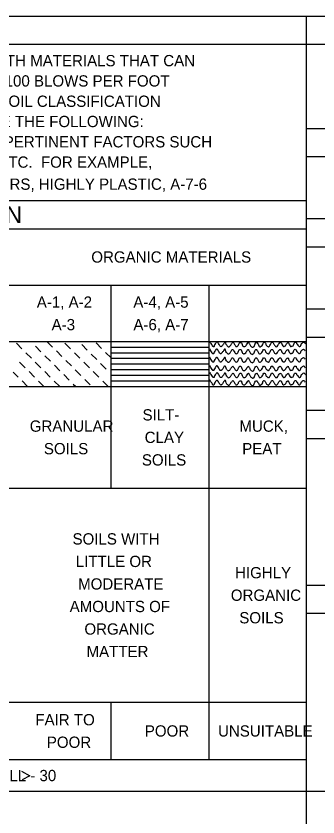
# Model space of a CAD drawing. Extents: x 265553 to 275568, y 168312 to 173522.
# Drawn here: x 267186.1 to 267302.4, y 170743.9 to 171052.1 of the extents above; entities that cross this region are included whole.
import ezdxf

# ---------------------------------------------------------------- set-up
doc = ezdxf.new("R2010")
doc.units = 0
doc.layers.add('Geotech Sheets and Borders Cell', color=7, linetype='Continuous')

msp = doc.modelspace()

# ---------------------------------------------------------------- linework, layer by layer
at = {"layer": 'Geotech Sheets and Borders Cell'}
for p, q in [((266920.42, 171052.08), (268420.42, 171052.08)), ((267297.82, 171052.08), (267297.82, 170249.94)), ((266920.42, 171041.24), (268420.42, 171041.24)), ((267670.42, 171008.7), (267297.82, 171008.7)), ((267670.42, 170997.86), (267297.82, 170997.86)), ((266920.42, 170981.07), (267297.82, 170981.07)), ((267670.42, 170974), (267297.82, 170974)), ((266920.42, 170970.22), (267297.82, 170970.22)), ((267670.42, 170963.15), (267297.82, 170963.15)), ((266920.42, 170948.53), (267297.82, 170948.53)), ((267222.78, 170870.45), (267222.78, 170948.53)), ((267260.52, 170765.99), (267260.52, 170948.53)), ((267670.42, 170939.29), (267297.82, 170939.29)), ((266920.42, 170926.84), (267297.82, 170926.84)), ((267188.37, 170924.06), (267186.25, 170926.19)), ((267198.01, 170926.84), (267200.13, 170924.72)), ((267207.07, 170924.06), (267204.95, 170926.19)), ((267211.41, 170925.67), (267213.54, 170923.54)), ((267219.09, 170924.19), (267216.96, 170926.32)), ((267670.42, 170928.45), (267297.82, 170928.45)), ((267192.02, 170920.42), (267189.89, 170922.55)), ((267195.71, 170922.89), (267193.58, 170925.02)), ((267201.65, 170923.2), (267203.77, 170921.07)), ((267210.72, 170920.42), (267208.59, 170922.55)), ((267222.73, 170920.55), (267220.61, 170922.68)), ((267222.78, 170924.72), (267260.52, 170924.72)), ((267222.78, 170922.55), (267260.52, 170922.55)), ((267260.78, 170924.02), (267260.73, 170923.98)), ((267199.35, 170919.25), (267197.22, 170921.38)), ((267205.29, 170919.55), (267207.42, 170917.43)), ((267215.05, 170922.03), (267217.18, 170919.9)), ((267222.78, 170920.38), (267260.52, 170920.38)), ((267260.78, 170920.81), (267260.73, 170920.77)), ((267189.59, 170916.78), (267187.46, 170918.9)), ((267195.66, 170916.78), (267193.54, 170918.9)), ((267200.87, 170917.73), (267202.99, 170915.61)), ((267214.36, 170916.78), (267212.23, 170918.9)), ((267218.7, 170918.38), (267220.82, 170916.26)), ((267222.78, 170918.21), (267260.52, 170918.21)), ((267260.82, 170917.56), (267260.78, 170917.51)), ((267186.9, 170913.18), (267185.03, 170915.04)), ((267193.23, 170913.13), (267191.11, 170915.26)), ((267199.31, 170913.13), (267197.18, 170915.26)), ((267204.51, 170914.09), (267206.64, 170911.96)), ((267208.94, 170915.91), (267211.06, 170913.78)), ((267218, 170913.13), (267215.88, 170915.26)), ((267222.78, 170916.04), (267260.52, 170916.04)), ((267222.78, 170913.87), (267260.52, 170913.87)), ((267260.91, 170914.87), (267260.86, 170914.82)), ((267190.54, 170909.53), (267188.42, 170911.66)), ((267196.88, 170909.49), (267194.75, 170911.61)), ((267202.95, 170909.49), (267200.82, 170911.61)), ((267208.16, 170910.44), (267209.15, 170909.49)), ((267212.58, 170912.27), (267214.71, 170910.14)), ((267221.65, 170909.49), (267219.52, 170911.61)), ((267222.78, 170911.7), (267260.52, 170911.7)), ((267260.56, 170911.27), (267260.52, 170911.31)), ((267260.6, 170911.7), (267260.56, 170911.66)), ((267260.86, 170912.01), (267260.82, 170911.96)), ((266920.42, 170909.49), (267297.82, 170909.49)), ((267670.42, 170900.25), (267297.82, 170900.25)), ((267670.42, 170889.41), (267297.82, 170889.41)), ((266920.42, 170870.45), (267297.82, 170870.45)), ((267670.42, 170833.01), (267297.82, 170833.01)), ((267670.42, 170822.17), (267297.82, 170822.17)), ((266920.42, 170788.03), (267297.82, 170788.03)), ((267222.78, 170765.99), (267222.78, 170788.03)), ((266920.42, 170765.99), (267297.82, 170765.99)), ((267670.42, 170753.71), (266920.42, 170753.71))]:
    msp.add_line(p, q, dxfattribs=at)
msp.add_lwpolyline([(267188.27, 170761.57), (267191.39, 170759.75), (267188.48, 170758.19)], dxfattribs=at)
for points in [[(267267.54, 170925.06), (267267.28, 170925.41), (267266.98, 170926.15), (267266.81, 170926.58), (267266.63, 170926.62), (267266.42, 170926.49), (267266.11, 170926.02), (267265.5, 170925.15), (267265.29, 170924.93), (267265.03, 170924.85), (267264.85, 170924.93), (267264.68, 170925.15), (267263.94, 170926.36), (267263.77, 170926.58), (267263.68, 170926.62), (267263.47, 170926.62), (267263.21, 170926.45), (267262.86, 170925.89), (267262.42, 170925.15), (267262.38, 170924.93), (267262.12, 170924.85), (267261.9, 170924.98), (267261.77, 170925.24), (267261.25, 170926.02), (267260.86, 170926.71)], [(267267.59, 170925.06), (267267.89, 170924.8), (267268.5, 170925.02), (267268.8, 170925.5), (267269.41, 170926.32), (267269.67, 170926.54), (267270.02, 170926.19), (267270.32, 170925.67), (267270.67, 170925.15), (267271.01, 170924.89), (267271.45, 170925.02), (267271.79, 170925.54), (267272.45, 170926.49), (267272.79, 170926.49), (267273.05, 170926.06), (267273.75, 170924.93), (267274.09, 170924.89), (267274.44, 170925.02), (267275.44, 170926.32), (267275.7, 170926.54), (267275.83, 170926.32), (267276.09, 170925.93), (267276.61, 170925.02), (267277.48, 170924.67), (267277.78, 170924.93), (267278.39, 170926.28), (267278.87, 170926.49), (267279.04, 170926.28), (267279.65, 170925.24), (267279.99, 170924.8), (267280.56, 170925.02), (267281.16, 170925.76), (267281.51, 170926.49), (267281.82, 170926.54), (267282.16, 170926.15), (267282.68, 170925.24), (267283.16, 170924.93), (267283.46, 170924.8), (267283.9, 170925.37), (267284.29, 170925.93), (267284.55, 170926.49), (267284.94, 170926.54), (267285.16, 170926.32), (267285.72, 170925.41), (267286.07, 170924.93), (267286.67, 170924.93), (267287.19, 170925.8), (267287.72, 170926.41), (267287.89, 170926.54), (267288.32, 170926.19), (267288.63, 170925.54), (267289.15, 170924.93), (267289.58, 170925.02), (267290.1, 170925.5), (267290.62, 170926.32), (267290.84, 170926.41), (267290.97, 170926.49), (267291.14, 170926.19), (267291.36, 170925.8), (267292.05, 170924.93), (267292.23, 170925.02), (267292.53, 170925.02), (267293.27, 170926.15), (267293.53, 170926.54), (267294.05, 170926.49), (267294.18, 170926.06), (267294.66, 170925.5), (267295.13, 170924.93), (267295.44, 170924.93), (267295.78, 170925.28), (267296.09, 170926.02)], [(267296.09, 170926.02), (267296.56, 170926.41), (267296.96, 170926.62), (267297.3, 170926.32), (267297.56, 170925.93)], [(267267.41, 170922.33), (267267.15, 170922.68), (267266.85, 170923.41), (267266.68, 170923.85), (267266.5, 170923.89), (267266.29, 170923.76), (267265.98, 170923.28), (267265.37, 170922.42), (267265.16, 170922.2), (267264.9, 170922.11), (267264.72, 170922.2), (267264.55, 170922.42), (267263.81, 170923.63), (267263.64, 170923.85), (267263.55, 170923.89), (267263.34, 170923.89), (267263.08, 170923.72), (267262.73, 170923.15), (267262.29, 170922.42), (267262.25, 170922.2), (267261.99, 170922.11), (267261.77, 170922.24), (267261.64, 170922.5), (267261.12, 170923.28), (267260.73, 170923.98)], [(267267.46, 170922.33), (267267.76, 170922.07), (267268.37, 170922.29), (267268.67, 170922.76), (267269.28, 170923.59), (267269.54, 170923.8), (267269.89, 170923.46), (267270.19, 170922.94), (267270.54, 170922.42), (267270.88, 170922.16), (267271.32, 170922.29), (267271.66, 170922.81), (267272.32, 170923.76), (267272.66, 170923.76), (267272.92, 170923.33), (267273.62, 170922.2), (267273.96, 170922.16), (267274.31, 170922.29), (267275.31, 170923.59), (267275.57, 170923.8), (267275.7, 170923.59), (267275.96, 170923.2), (267276.48, 170922.29), (267277.35, 170921.94), (267277.65, 170922.2), (267278.26, 170923.54), (267278.74, 170923.76), (267278.91, 170923.54), (267279.52, 170922.5), (267279.86, 170922.07), (267280.43, 170922.29), (267281.03, 170923.02), (267281.38, 170923.76), (267281.69, 170923.8), (267282.03, 170923.41), (267282.55, 170922.5), (267283.03, 170922.2), (267283.33, 170922.07), (267283.77, 170922.63), (267284.16, 170923.2), (267284.42, 170923.76), (267284.81, 170923.8), (267285.03, 170923.59), (267285.59, 170922.68), (267285.94, 170922.2), (267286.54, 170922.2), (267287.06, 170923.07), (267287.58, 170923.67), (267287.76, 170923.8), (267288.19, 170923.46), (267288.5, 170922.81), (267289.02, 170922.2), (267289.45, 170922.29), (267289.97, 170922.76), (267290.49, 170923.59), (267290.71, 170923.67), (267290.84, 170923.76), (267291.01, 170923.46), (267291.23, 170923.07), (267291.92, 170922.2), (267292.1, 170922.29), (267292.4, 170922.29), (267293.14, 170923.41), (267293.4, 170923.8), (267293.92, 170923.76), (267294.05, 170923.33), (267294.53, 170922.76), (267295, 170922.2), (267295.31, 170922.2), (267295.65, 170922.55), (267295.96, 170923.28)], [(267295.96, 170923.28), (267296.43, 170923.67), (267296.82, 170923.89), (267297.17, 170923.59), (267297.43, 170923.2)], [(267267.41, 170919.12), (267267.15, 170919.47), (267266.85, 170920.2), (267266.68, 170920.64), (267266.5, 170920.68), (267266.29, 170920.55), (267265.98, 170920.07), (267265.37, 170919.21), (267265.16, 170918.99), (267264.9, 170918.9), (267264.72, 170918.99), (267264.55, 170919.21), (267263.81, 170920.42), (267263.64, 170920.64), (267263.55, 170920.68), (267263.34, 170920.68), (267263.08, 170920.51), (267262.73, 170919.94), (267262.29, 170919.21), (267262.25, 170918.99), (267261.99, 170918.9), (267261.77, 170919.03), (267261.64, 170919.29), (267261.12, 170920.07), (267260.73, 170920.77)], [(267267.46, 170919.12), (267267.76, 170918.86), (267268.37, 170919.08), (267268.67, 170919.55), (267269.28, 170920.38), (267269.54, 170920.59), (267269.89, 170920.25), (267270.19, 170919.73), (267270.54, 170919.21), (267270.88, 170918.95), (267271.32, 170919.08), (267271.66, 170919.6), (267272.32, 170920.55), (267272.66, 170920.55), (267272.92, 170920.12), (267273.62, 170918.99), (267273.96, 170918.95), (267274.31, 170919.08), (267275.31, 170920.38), (267275.57, 170920.59), (267275.7, 170920.38), (267275.96, 170919.99), (267276.48, 170919.08), (267277.35, 170918.73), (267277.65, 170918.99), (267278.26, 170920.33), (267278.74, 170920.55), (267278.91, 170920.33), (267279.52, 170919.29), (267279.86, 170918.86), (267280.43, 170919.08), (267281.03, 170919.81), (267281.38, 170920.55), (267281.69, 170920.59), (267282.03, 170920.2), (267282.55, 170919.29), (267283.03, 170918.99), (267283.33, 170918.86), (267283.77, 170919.42), (267284.16, 170919.99), (267284.42, 170920.55), (267284.81, 170920.59), (267285.03, 170920.38), (267285.59, 170919.47), (267285.94, 170918.99), (267286.54, 170918.99), (267287.06, 170919.86), (267287.58, 170920.46), (267287.76, 170920.59), (267288.19, 170920.25), (267288.5, 170919.6), (267289.02, 170918.99), (267289.45, 170919.08), (267289.97, 170919.55), (267290.49, 170920.38), (267290.71, 170920.46), (267290.84, 170920.55), (267291.01, 170920.25), (267291.23, 170919.86), (267291.92, 170918.99), (267292.1, 170919.08), (267292.4, 170919.08), (267293.14, 170920.2), (267293.4, 170920.59), (267293.92, 170920.55), (267294.05, 170920.12), (267294.53, 170919.55), (267295, 170918.99), (267295.31, 170918.99), (267295.65, 170919.34), (267295.96, 170920.07)], [(267295.96, 170920.07), (267296.43, 170920.46), (267296.82, 170920.68), (267297.17, 170920.38), (267297.43, 170919.99)], [(267267.46, 170915.87), (267267.2, 170916.21), (267266.89, 170916.95), (267266.72, 170917.38), (267266.55, 170917.43), (267266.33, 170917.3), (267266.03, 170916.82), (267265.42, 170915.95), (267265.2, 170915.74), (267264.94, 170915.65), (267264.77, 170915.74), (267264.59, 170915.95), (267263.86, 170917.17), (267263.68, 170917.38), (267263.6, 170917.43), (267263.38, 170917.43), (267263.12, 170917.25), (267262.77, 170916.69), (267262.34, 170915.95), (267262.29, 170915.74), (267262.03, 170915.65), (267261.82, 170915.78), (267261.69, 170916.04), (267261.17, 170916.82), (267260.78, 170917.51)], [(267267.5, 170915.87), (267267.8, 170915.61), (267268.41, 170915.82), (267268.71, 170916.3), (267269.32, 170917.12), (267269.58, 170917.34), (267269.93, 170916.99), (267270.23, 170916.47), (267270.58, 170915.95), (267270.93, 170915.69), (267271.36, 170915.82), (267271.71, 170916.34), (267272.36, 170917.3), (267272.71, 170917.3), (267272.97, 170916.86), (267273.66, 170915.74), (267274.01, 170915.69), (267274.35, 170915.82), (267275.35, 170917.12), (267275.61, 170917.34), (267275.74, 170917.12), (267276, 170916.73), (267276.52, 170915.82), (267277.39, 170915.48), (267277.69, 170915.74), (267278.3, 170917.08), (267278.78, 170917.3), (267278.95, 170917.08), (267279.56, 170916.04), (267279.91, 170915.61), (267280.47, 170915.82), (267281.08, 170916.56), (267281.43, 170917.3), (267281.73, 170917.34), (267282.08, 170916.95), (267282.6, 170916.04), (267283.07, 170915.74), (267283.38, 170915.61), (267283.81, 170916.17), (267284.2, 170916.73), (267284.46, 170917.3), (267284.85, 170917.34), (267285.07, 170917.12), (267285.63, 170916.21), (267285.98, 170915.74), (267286.59, 170915.74), (267287.11, 170916.6), (267287.63, 170917.21), (267287.8, 170917.34), (267288.24, 170916.99), (267288.54, 170916.34), (267289.06, 170915.74), (267289.49, 170915.82), (267290.01, 170916.3), (267290.53, 170917.12), (267290.75, 170917.21), (267290.88, 170917.3), (267291.06, 170916.99), (267291.27, 170916.6), (267291.97, 170915.74), (267292.14, 170915.82), (267292.44, 170915.82), (267293.18, 170916.95), (267293.44, 170917.34), (267293.96, 170917.3), (267294.09, 170916.86), (267294.57, 170916.3), (267295.05, 170915.74), (267295.35, 170915.74), (267295.7, 170916.08), (267296, 170916.82)], [(267296, 170916.82), (267296.48, 170917.21), (267296.87, 170917.43), (267297.22, 170917.12), (267297.48, 170916.73)], [(267267.54, 170913.18), (267267.28, 170913.52), (267266.98, 170914.26), (267266.81, 170914.69), (267266.63, 170914.74), (267266.42, 170914.61), (267266.11, 170914.13), (267265.5, 170913.26), (267265.29, 170913.05), (267265.03, 170912.96), (267264.85, 170913.05), (267264.68, 170913.26), (267263.94, 170914.48), (267263.77, 170914.69), (267263.68, 170914.74), (267263.47, 170914.74), (267263.21, 170914.56), (267262.86, 170914), (267262.42, 170913.26), (267262.38, 170913.05), (267262.12, 170912.96), (267261.9, 170913.09), (267261.77, 170913.35), (267261.25, 170914.13), (267260.86, 170914.82)], [(267267.59, 170913.18), (267267.89, 170912.92), (267268.5, 170913.13), (267268.8, 170913.61), (267269.41, 170914.43), (267269.67, 170914.65), (267270.02, 170914.3), (267270.32, 170913.78), (267270.67, 170913.26), (267271.01, 170913), (267271.45, 170913.13), (267271.79, 170913.65), (267272.45, 170914.61), (267272.79, 170914.61), (267273.05, 170914.17), (267273.75, 170913.05), (267274.09, 170913), (267274.44, 170913.13), (267275.44, 170914.43), (267275.7, 170914.65), (267275.83, 170914.43), (267276.09, 170914.04), (267276.61, 170913.13), (267277.48, 170912.79), (267277.78, 170913.05), (267278.39, 170914.39), (267278.87, 170914.61), (267279.04, 170914.39), (267279.65, 170913.35), (267279.99, 170912.92), (267280.56, 170913.13), (267281.16, 170913.87), (267281.51, 170914.61), (267281.82, 170914.65), (267282.16, 170914.26), (267282.68, 170913.35), (267283.16, 170913.05), (267283.46, 170912.92), (267283.9, 170913.48), (267284.29, 170914.04), (267284.55, 170914.61), (267284.94, 170914.65), (267285.16, 170914.43), (267285.72, 170913.52), (267286.07, 170913.05), (267286.67, 170913.05), (267287.19, 170913.91), (267287.72, 170914.52), (267287.89, 170914.65), (267288.32, 170914.3), (267288.63, 170913.65), (267289.15, 170913.05), (267289.58, 170913.13), (267290.1, 170913.61), (267290.62, 170914.43), (267290.84, 170914.52), (267290.97, 170914.61), (267291.14, 170914.3), (267291.36, 170913.91), (267292.05, 170913.05), (267292.23, 170913.13), (267292.53, 170913.13), (267293.27, 170914.26), (267293.53, 170914.65), (267294.05, 170914.61), (267294.18, 170914.17), (267294.66, 170913.61), (267295.13, 170913.05), (267295.44, 170913.05), (267295.78, 170913.39), (267296.09, 170914.13)], [(267296.09, 170914.13), (267296.56, 170914.52), (267296.96, 170914.74), (267297.3, 170914.43), (267297.56, 170914.04)], [(267267.5, 170910.31), (267267.24, 170910.66), (267266.94, 170911.4), (267266.76, 170911.83), (267266.59, 170911.87), (267266.37, 170911.74), (267266.07, 170911.27), (267265.46, 170910.4), (267265.24, 170910.18), (267264.98, 170910.1), (267264.81, 170910.18), (267264.64, 170910.4), (267263.9, 170911.61), (267263.73, 170911.83), (267263.64, 170911.87), (267263.42, 170911.87), (267263.16, 170911.7), (267262.82, 170911.14), (267262.38, 170910.4), (267262.34, 170910.18), (267262.08, 170910.1), (267261.86, 170910.23), (267261.73, 170910.49), (267261.21, 170911.27), (267260.82, 170911.96)], [(267267.54, 170910.31), (267267.85, 170910.05), (267268.45, 170910.27), (267268.76, 170910.75), (267269.37, 170911.57), (267269.63, 170911.79), (267269.97, 170911.44), (267270.28, 170910.92), (267270.62, 170910.4), (267270.97, 170910.14), (267271.4, 170910.27), (267271.75, 170910.79), (267272.4, 170911.74), (267272.75, 170911.74), (267273.01, 170911.31), (267273.7, 170910.18), (267274.05, 170910.14), (267274.4, 170910.27), (267275.4, 170911.57), (267275.66, 170911.79), (267275.79, 170911.57), (267276.05, 170911.18), (267276.57, 170910.27), (267277.43, 170909.92), (267277.74, 170910.18), (267278.35, 170911.53), (267278.82, 170911.74), (267279, 170911.53), (267279.6, 170910.49), (267279.95, 170910.05), (267280.51, 170910.27), (267281.12, 170911.01), (267281.47, 170911.74), (267281.77, 170911.79), (267282.12, 170911.4), (267282.64, 170910.49), (267283.12, 170910.18), (267283.42, 170910.05), (267283.85, 170910.62), (267284.24, 170911.18), (267284.51, 170911.74), (267284.9, 170911.79), (267285.11, 170911.57), (267285.68, 170910.66), (267286.02, 170910.18), (267286.63, 170910.18), (267287.15, 170911.05), (267287.67, 170911.66), (267287.85, 170911.79), (267288.28, 170911.44), (267288.58, 170910.79), (267289.1, 170910.18), (267289.54, 170910.27), (267290.06, 170910.75), (267290.58, 170911.57), (267290.8, 170911.66), (267290.93, 170911.74), (267291.1, 170911.44), (267291.32, 170911.05), (267292.01, 170910.18), (267292.18, 170910.27), (267292.49, 170910.27), (267293.22, 170911.4), (267293.48, 170911.79), (267294.01, 170911.74), (267294.14, 170911.31), (267294.61, 170910.75), (267295.09, 170910.18), (267295.39, 170910.18), (267295.74, 170910.53), (267296.04, 170911.27)], [(267296.04, 170911.27), (267296.52, 170911.66), (267296.91, 170911.87), (267297.26, 170911.57), (267297.52, 170911.18)]]:
    msp.add_spline(points, degree=3, dxfattribs=at)

# ---------------------------------------------------------------- texts
for s, height, p in [('SOIL IS CONSIDERED UNCONSOLIDATED, SEMI-CONSOLIDATED, OR WEATHERED EARTH MATERIALS THAT CAN', 4.3381, (266936.62, 171032.75)), ('BE PENETRATED WITH A CONTINUOUS FLIGHT POWER AUGER AND YIELD LESS THAN 100 BLOWS PER FOOT', 4.3381, (266935.16, 171024.94)), ('ACCORDING TO THE STANDARD PENETRATION TEST (AASHTO T 206, ASTM D1586).  SOIL CLASSIFICATION', 4.3381, (266939.51, 171017.13)), ('IS BASED ON THE AASHTO SYSTEM.  BASIC DESCRIPTIONS GENERALLY INCLUDE THE FOLLOWING:', 4.3381, (266951.98, 171009.33)), ('CONSISTENCY, COLOR, TEXTURE, MOISTURE, AASHTO CLASSIFICATION, AND OTHER PERTINENT FACTORS SUCH ', 4.3381, (266936.1, 171001.52)), ('AS MINERALOGICAL COMPOSITION, ANGULARITY, STRUCTURE, PLASTICITY, ETC.  FOR EXAMPLE,', 4.3381, (266960.42, 170993.71)), ('VERY STIFF, GRAY, SILTY CLAY, MOIST WITH INTERBEDDED FINE SAND LAYERS, HIGHLY PLASTIC, A-7-6', 4.3381, (266964.1, 170985.22)), ('SOIL LEGEND AND AASHTO CLASSIFICATION', 6.507, (266997.45, 170972.39)), ('ORGANIC MATERIALS', 4.3381, (267215.11, 170957.2)), ('A-1, A-2', 4.338, (267194.11, 170939.85)), ('A-4, A-5', 4.338, (267231.3, 170939.85)), ('A-3', 4.338, (267199.82, 170931.18)), ('A-6, A-7', 4.338, (267231.33, 170931.18)), ('SILT-', 4.338, (267234.84, 170896.46)), ('GRANULAR', 4.338, (267191.4, 170892.13)), ('MUCK,', 4.338, (267272.17, 170892.13)), ('CLAY', 4.338, (267235.67, 170887.8)), ('SOILS', 4.338, (267196.84, 170883.46)), ('PEAT', 4.338, (267273.23, 170883.46)), ('SOILS', 4.338, (267234.59, 170879.13)), ('SOILS WITH', 4.338, (267207.88, 170848.74)), ('LITTLE OR', 4.338, (267209.14, 170840.07)), ('HIGHLY', 4.338, (267270.48, 170835.73)), ('MODERATE', 4.338, (267210.03, 170831.4)), ('ORGANIC', 4.338, (267268.85, 170827.07)), ('AMOUNTS OF', 4.338, (267206.77, 170822.73)), ('SOILS', 4.338, (267272.11, 170818.4)), ('ORGANIC', 4.338, (267212.45, 170814.06)), ('MATTER', 4.338, (267213.27, 170805.4)), ('FAIR TO', 4.338, (267193.56, 170779.17)), ('POOR', 4.338, (267235.72, 170774.84)), ('UNSUITABLE', 4.338, (267263.93, 170774.84)), ('POOR', 4.338, (267197.97, 170770.5)), ('PI OF A-7-5 SUBGROUP IS    LL - 30 ; PI OF A-7-6 SUBGROUP IS   LL - 30', 4.3381, (267003.66, 170757.68))]:
    msp.add_text(s, height=height, dxfattribs=at).set_placement(p)

doc.saveas('drawing.dxf')
